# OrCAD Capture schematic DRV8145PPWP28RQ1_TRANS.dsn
size Custom; title: DRV8145-Q1 Automotive Half Bridge Driver with; rev: 1.0; note: Datasheet: SLVSG22      EVM: NA; note: Synchronous Step Down Converter
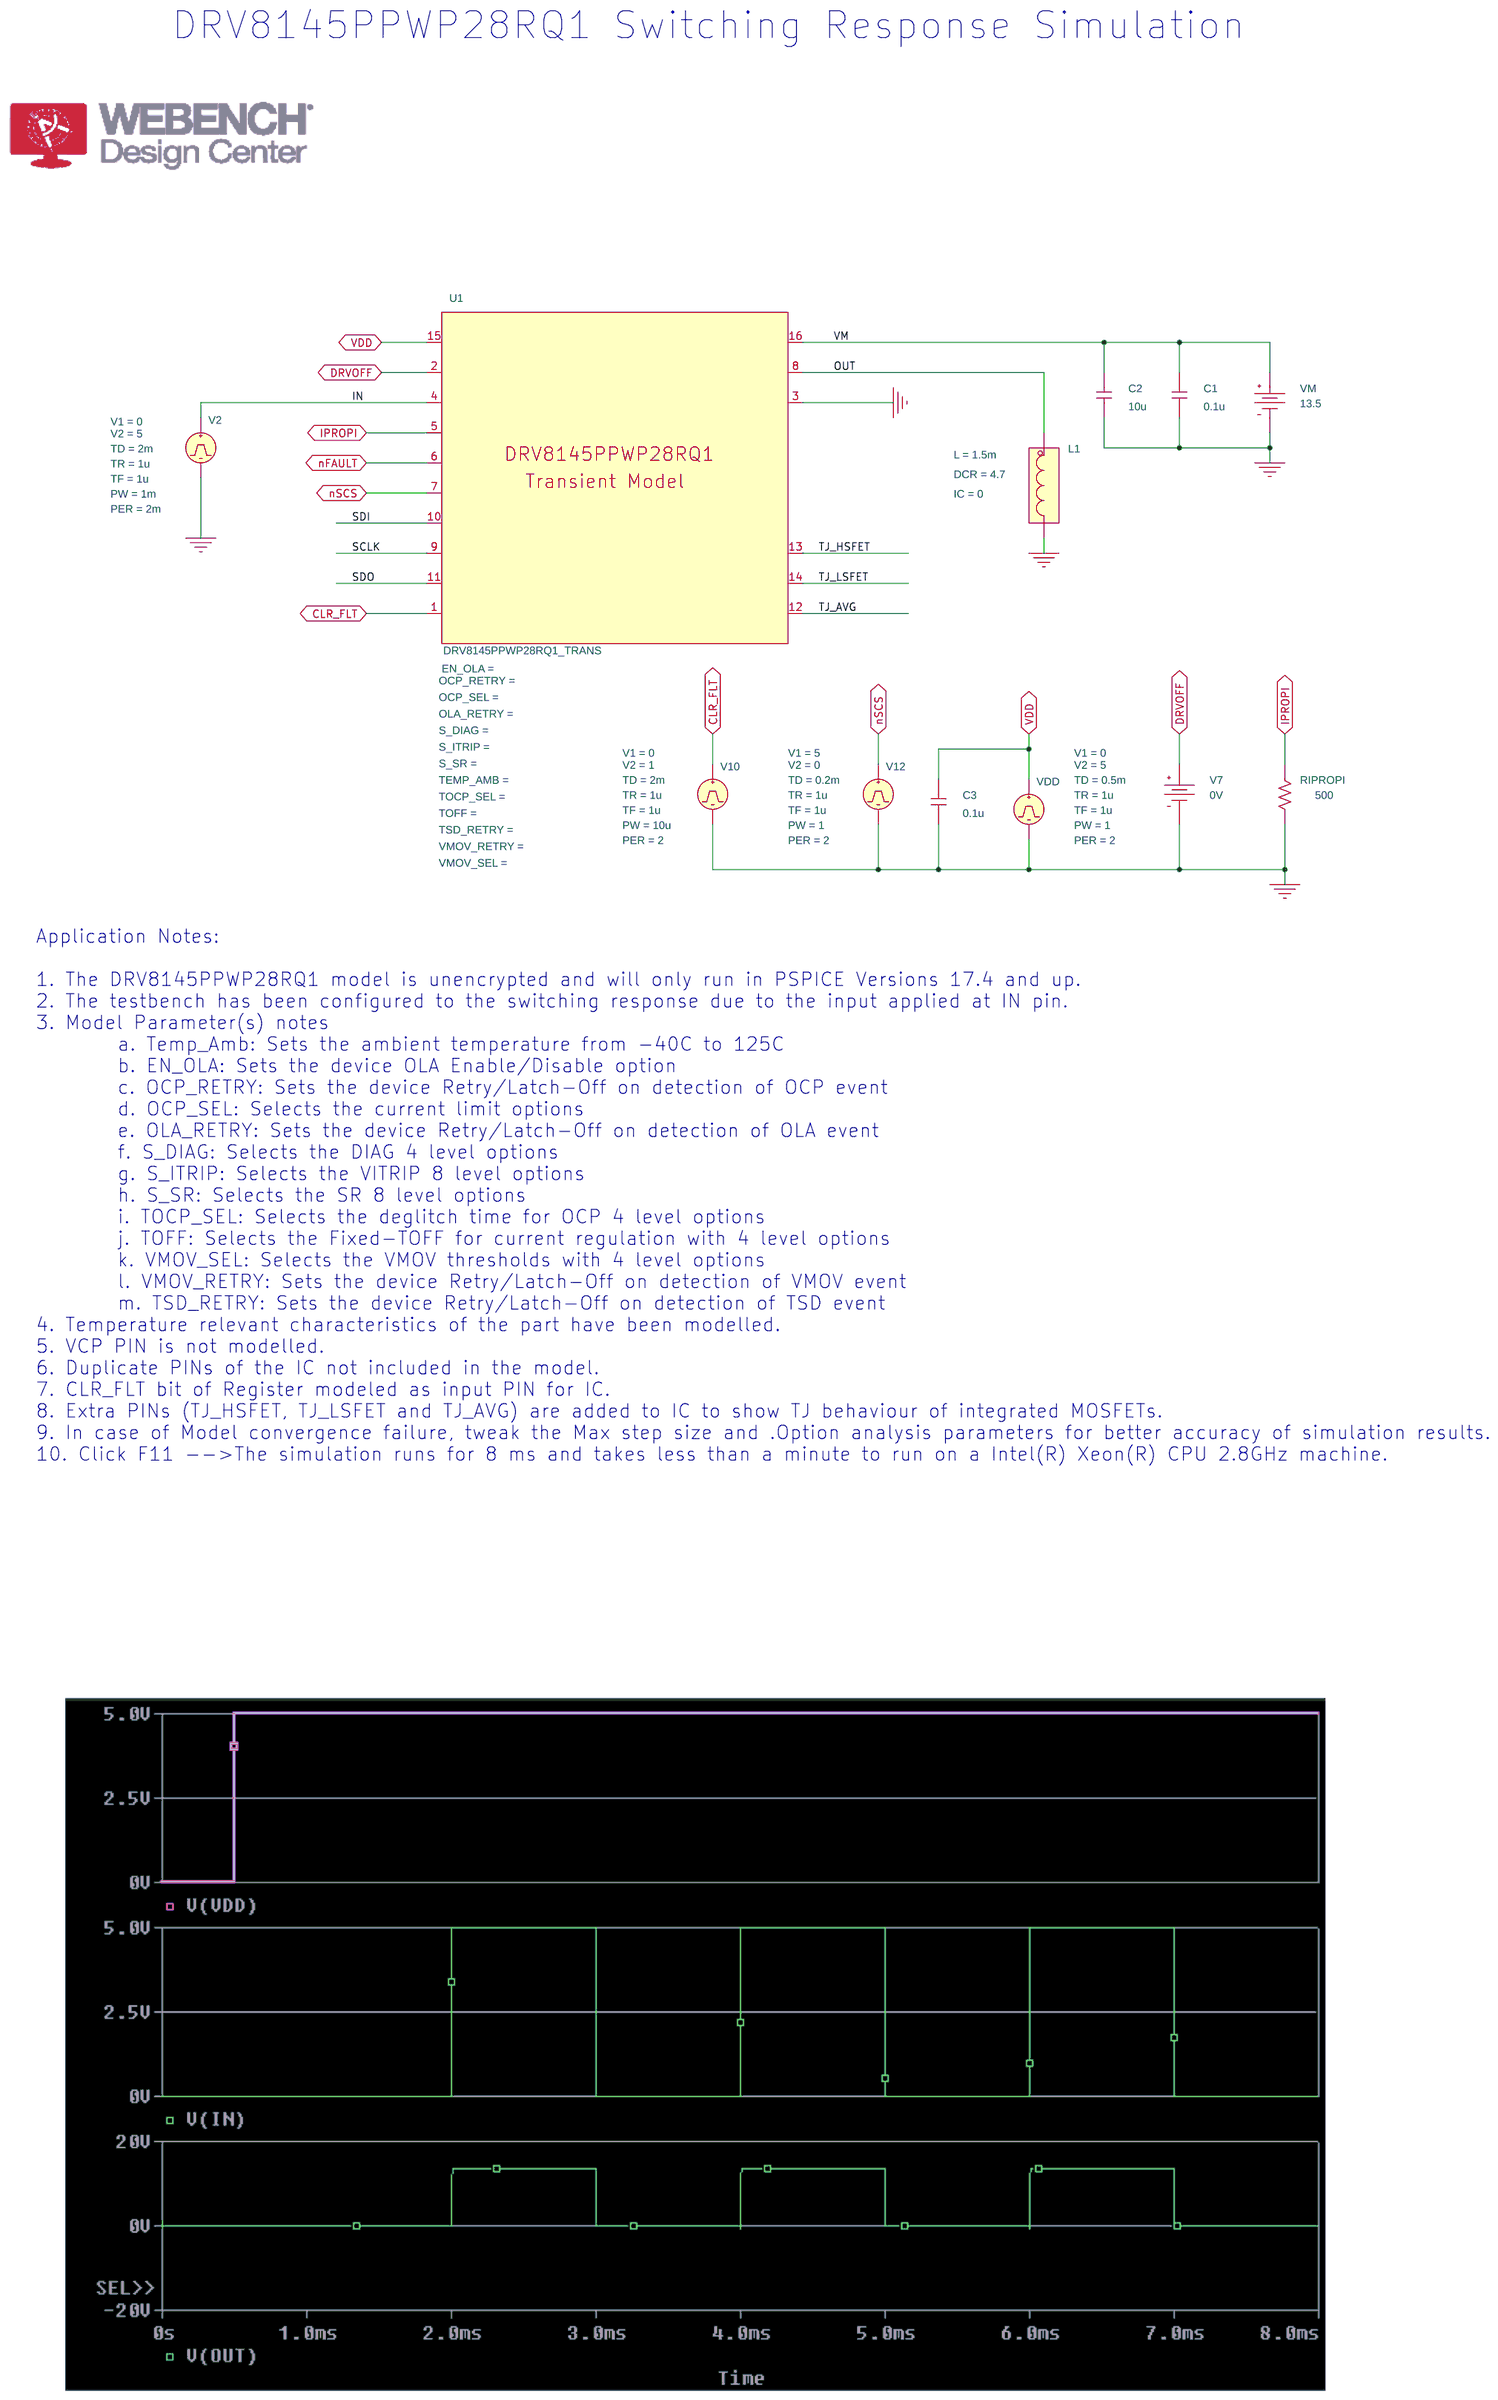
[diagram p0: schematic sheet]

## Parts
C1  0.1u  [RAD/CK05]
C2  10u  [RAD/CK05]
C3  0.1u  [RAD/CK05]
L1  LDCR
RIPROPI  500  [AXRC05]
U1  DRV8145PPWP28RQ1_TRANS
V2  VPULSE
V7  VDC
V10  VPULSE
V12  VPULSE
VDD  VPULSE
VM  VDC

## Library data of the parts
C1-C3 = C
L1 = LDCR: DCR: 4.7; IC: 0; L: 1.5m; PSpiceTemplate: X^@REFDES %IN %OUT @MODEL PARAMS:  ?L|L=@L||L=1u|  ?DCR|DCR=@DCR||DCR=0.01| ?IC|IC=@IC||IC=0|
RIPROPI = R
U1 = DRV8145PPWP28RQ1_TRANS
V2 = VPULSE: PER: 2m; PW: 1m; TD: 2m; TF: 1u; TR: 1u; V1: 0; V2: 5
V7 = VDC: DC: 0V
V10 = VPULSE: PER: 2; PW: 10u; TD: 2m; TF: 1u; TR: 1u; V1: 0; V2: 1
V12 = VPULSE: PER: 2; PW: 1; TD: 0.2m; TF: 1u; TR: 1u; V1: 5; V2: 0
VDD = VPULSE: PER: 2; PW: 1; TD: 0.5m; TF: 1u; TR: 1u; V1: 0; V2: 5
VM = VDC: DC: 13.5

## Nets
VDD: C3.1 U1.15(VDD) VDD.1(+)
0: C1.2 C2.2 C3.2 L1.3(OUT) RIPROPI.2 U1.3(GND) V2.2(-) V7.1(-) V10.2(-) V12.2(-) VDD.2(-) VM.1(-)
CLR_FLT: U1.1(CLR_FLT) V10.1(+)
DRVOFF: U1.2(DRVOFF) V7.0(+)
IN: U1.4(IN) V2.1(+)
IPROPI: RIPROPI.1 U1.5(IPROPI)
nFAULT: U1.6(nFAULT)
nSCS: U1.7(nSCS) V12.1(+)
OUT: L1.1(IN) U1.8(OUT)
SCLK: U1.9(SCLK)
SDI: U1.10(SDI)
SDO: U1.11(SDO)
TJ_AVG: U1.12(TJ_AVG)
TJ_HSFET: U1.13(TJ_HSFET)
TJ_LSFET: U1.14(TJ_LSFET)
VM: C1.1 C2.1 U1.16(VM) VM.0(+)

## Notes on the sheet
- DRV8145PPWP28RQ1 Switching Response Simulation
- Application Notes:
  1. The DRV8145PPWP28RQ1 model is unencrypted and will only run in PSPICE Versions 17.4 and up.
  2. The testbench has been configured to the switching response due to the input applied at IN pin.
  3. Model Parameter(s) notes
          a. Temp_Amb: Sets the ambient temperature from -40C to 125C
          b. EN_OLA: Sets the device OLA Enable/Disable option
          c. OCP_RETRY: Sets the device Retry/Latch-Off on detection of OCP event
          d. OCP_SEL: Selects the current limit options
          e. OLA_RETRY: Sets the device Retry/Latch-Off on detection of OLA event
          f. S_DIAG: Selects the DIAG 4 level options
          g. S_ITRIP: Selects the VITRIP 8 level options
          h. S_SR: Selects the SR 8 level options
          i. TOCP_SEL: Selects the deglitch time for OCP 4 level options
          j. TOFF: Selects the Fixed-TOFF for current regulation with 4 level options
          k. VMOV_SEL: Selects the VMOV thresholds with 4 level options
          l. VMOV_RETRY: Sets the device Retry/Latch-Off on detection of VMOV event
          m. TSD_RETRY: Sets the device Retry/Latch-Off on detection of TSD event
  4. Temperature relevant characteristics of the part have been modelled.
  5. VCP PIN is not modelled.
  6. Duplicate PINs of the IC not included in the model.
  7. CLR_FLT bit of Register modeled as input PIN for IC.
  8. Extra PINs (TJ_HSFET, TJ_LSFET and TJ_AVG) are added to IC to show TJ behaviour of integrated MOSFETs.
  9. In case of Model convergence failure, tweak the Max step size and .Option analysis parameters for better accuracy of simulation results.
  10. Click F11 -->The simulation runs for 8 ms and takes less than a minute to run on a Intel(R) Xeon(R) CPU 2.8GHz machine.
